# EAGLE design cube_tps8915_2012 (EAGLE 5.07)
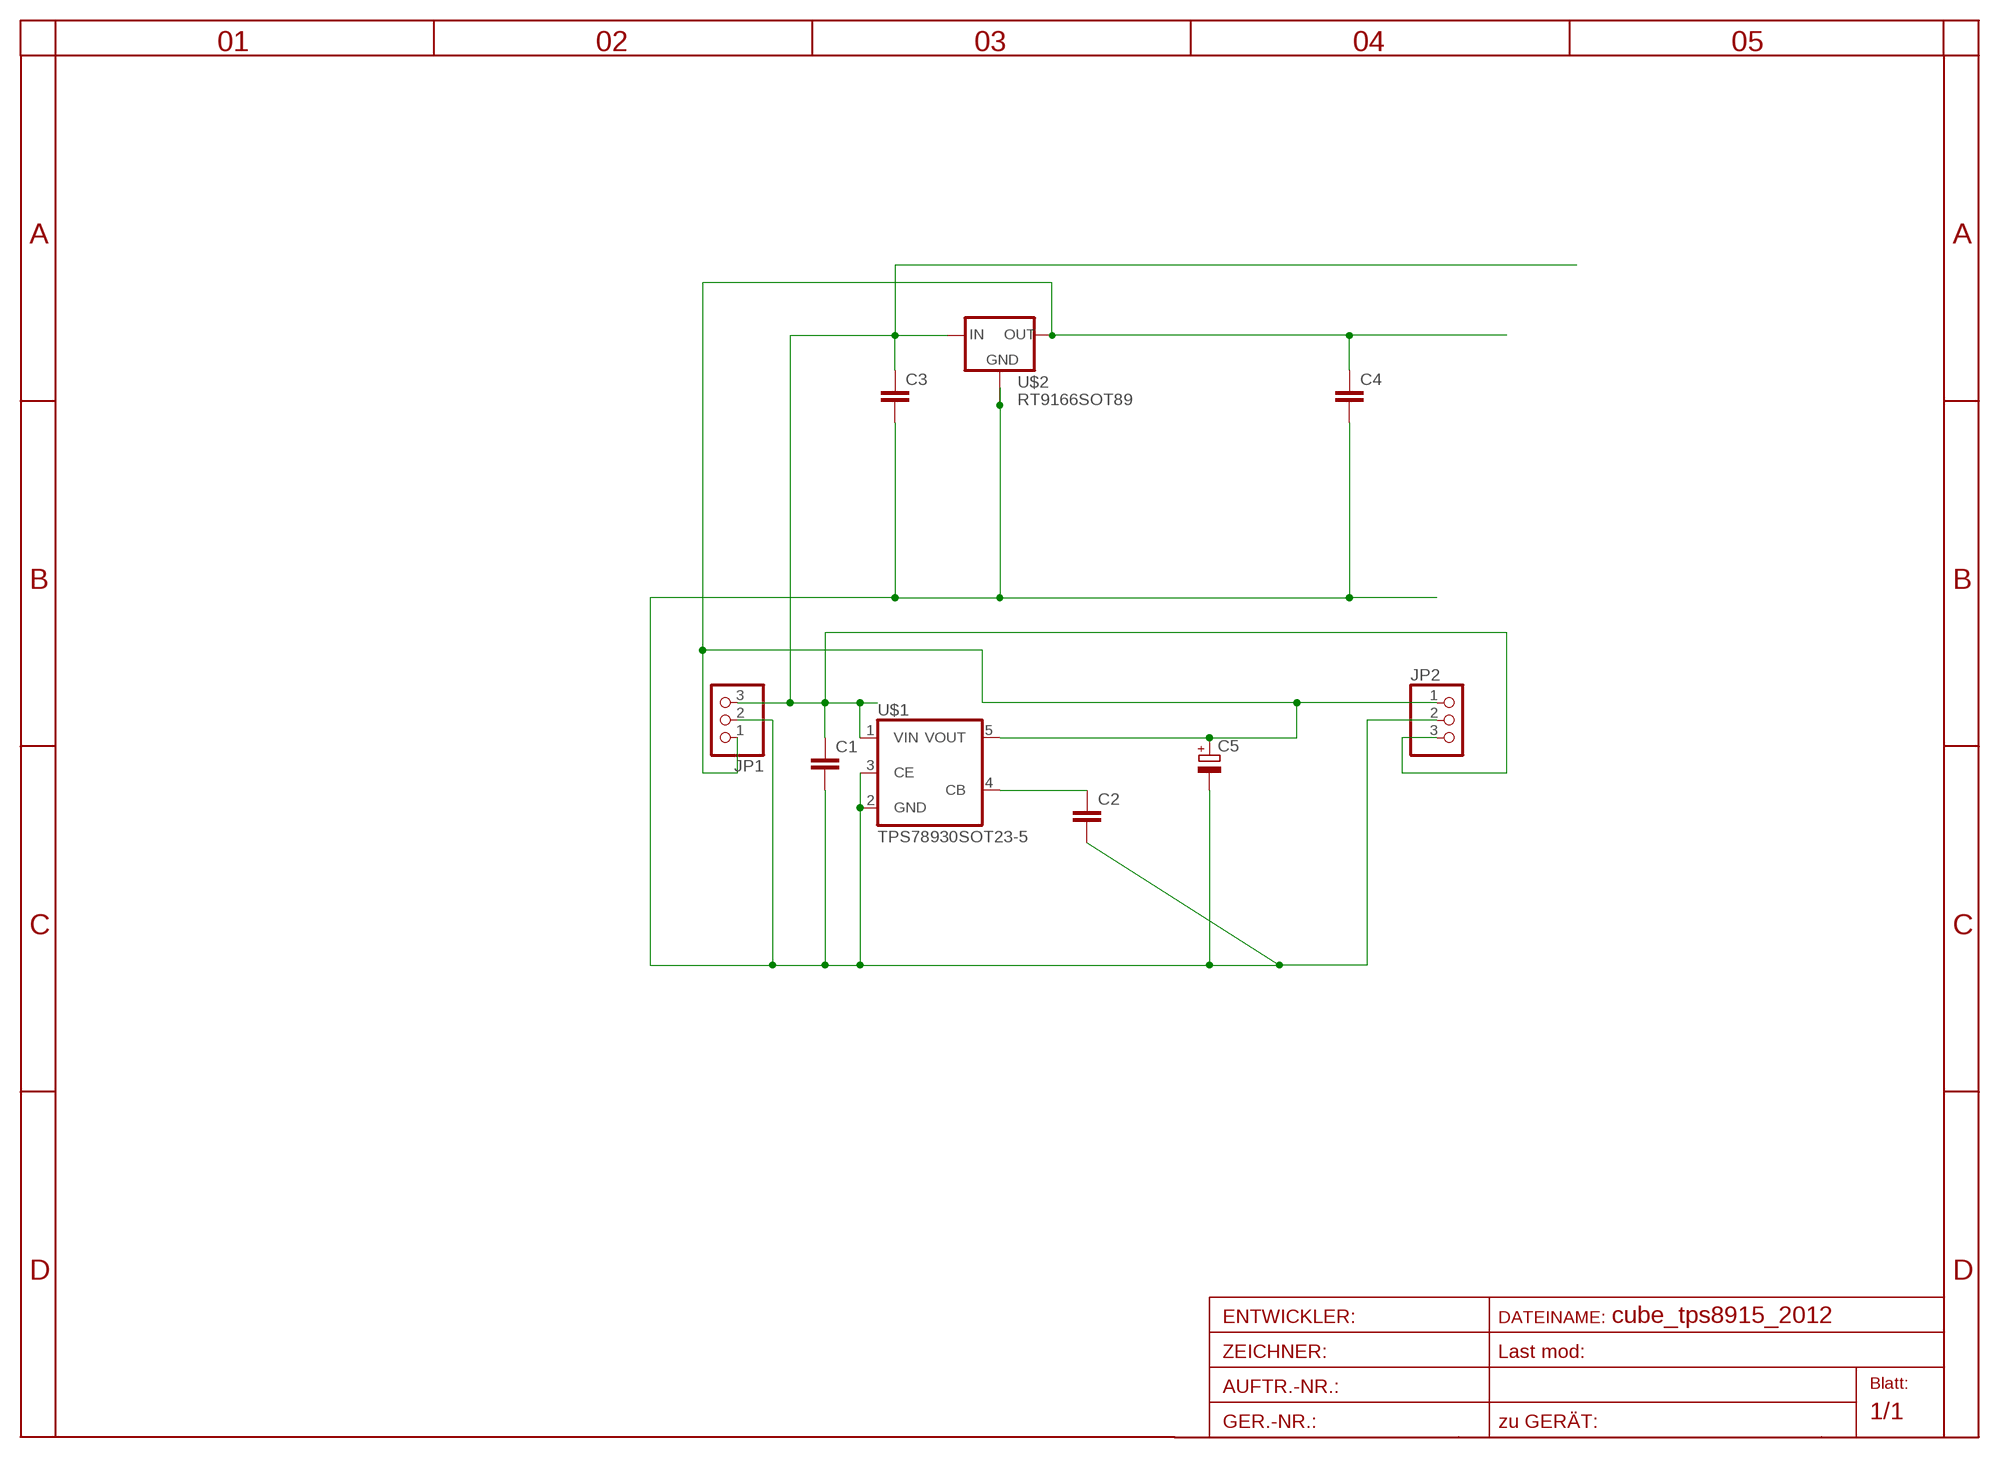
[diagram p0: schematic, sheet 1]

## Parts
C1  C-EUC0805  [C0805]
C2  C-EUC0805  [C0805]
C3  C-EUC1206  [C1206]
C4  C-EUC1206  [C1206]
C5  CPOL-EUCT6032  [CT6032]
JP1  PINHD-1X3  [1X03]
JP2  PINHD-1X3  [1X03]
U$1  TPS78930SOT23-5  [SOT25]
U$2  RT9166SOT89  [SOT89R]

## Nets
GND: C1.2 C2.2 C3.2 C4.2 C5.- JP1.2 JP2.2 U$1.2(GND) U$1.3(CE) U$2.3(GND) U$2.4(GND1)
IN: C1.1 C3.1 JP1.3 JP2.3 U$1.1(VIN) U$2.1(IN)
N$1: C2.1 U$1.4(CB)
OUT: C4.1 C5.+ JP1.1 JP2.1 U$1.5(VOUT) U$2.2(OUT)

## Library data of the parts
C1-C4 = rcl:C-EU: CAPACITOR, European symbol
C5 = rcl:CPOL-EU: POLARIZED CAPACITOR, European symbol
JP1 JP2 = pinhead:PINHD-1X3: PIN HEADER
U$1 = v-reg:TPS78930
U$2 = v-reg:RT9166

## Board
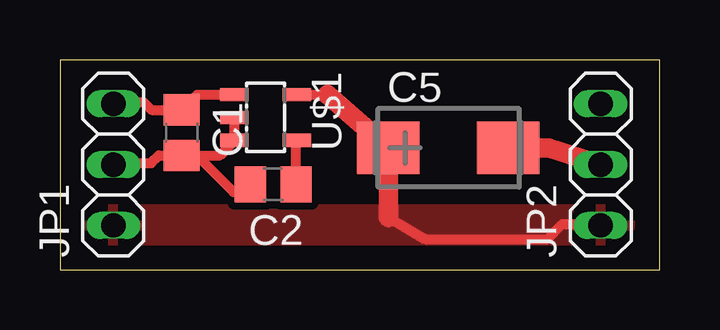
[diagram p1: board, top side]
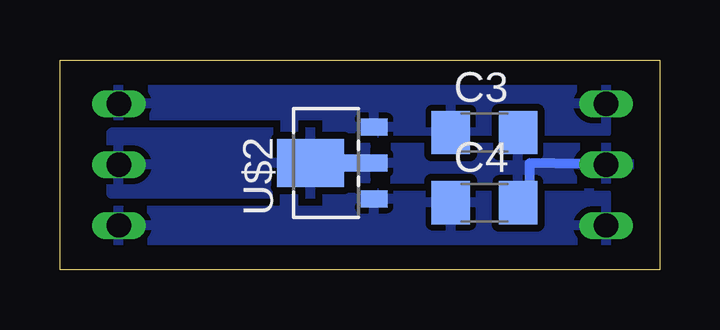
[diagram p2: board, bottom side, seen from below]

Size 25 x 8.75 mm. Coordinates in mm from the lower left corner, seen from the top.
Outline: 0,0 25,0 25,8.75 0,8.75 0,0
Copper layers (1*16): Top 0.035mm / dielectric 1.5mm / Bottom 0.035mm
Design rules "default": minimum track width 10mil, minimum drill 20mil, track to track 8mil, track to pad 8mil, pad to pad 8mil, via to via 8mil, smd to smd 8mil, copper to edge 40mil, drill to drill 8mil, minimum pad ring 1mil, minimum via ring 8mil, stop-mask expansion 4mil, vias tented up to drill 0mil, thermal gap 10mil

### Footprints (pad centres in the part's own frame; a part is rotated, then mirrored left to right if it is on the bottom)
C0805 = smd 1.3 x 1.5: 1 -0.95,0; 2 0.95,0
C1206 = smd 1.6 x 1.8: 1 -1.4,0; 2 1.4,0
CT6032 = smd 2.6 x 2.2: + -2.5,0; - 2.5,0
1X03 = drill 1.016 long: 1 -2.54,0; 2 0,0; 3 2.54,0
SOT25 = smd 0.55 x 1.2: 1 -0.95,-1.3; 2 0,-1.3; 3 0.95,-1.3; 4 0.95,1.3; 5 -0.95,1.3
SOT89R = smd 0.7 x 1.1: 1 1.5,-1.75; 2 -1.5,-1.75 | smd 0.7 x 1.8: 3 0,-1.4 | smd 2 x 2.8: 4 0,0.9

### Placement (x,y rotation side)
C1  5.08,5.71 270 top
C2  8.89,3.56 180 top
C3  7.3,5.71 0 bottom
C4  7.3,2.79 0 bottom
C5  16.19,5.08 0 top
JP1  2.22,4.38 90 top
JP2  22.54,4.38 90 top
U$1  8.57,6.35 270 top
U$2  13.65,4.45 90 bottom

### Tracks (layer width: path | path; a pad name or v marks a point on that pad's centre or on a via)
GND
  Top 0.406: JP1.2 2.29,4.45 3.81,4.45 4.13,4.76 C1.2 5.71,4.76 | 5.71,4.76 6.67,4.76 U$1.3 U$1.2 | C2.2 7.24,3.24 5.71,4.76
  Top 0.813: C5.- 20.38,5.08 JP2.2
  Bottom 0.406: C4.2 5.42,2.79 5.42,4.45 JP1.2
  pour Bottom (isolate 0.305): 1.27,5.08 11.43,5.08 12.7,5.71 22.86,5.71 22.86,3.17 13.97,3.17 12.7,3.81 1.27,3.81
IN
  Top 0.406: JP1.3 2.29,6.99 3.49,6.99 3.81,6.67 C1.1 5.71,7.3 U$1.1
  pour Bottom (isolate 0.305, rank 2): 2.22,5.71 2.22,8.26 22.86,8.26 22.86,5.71
N$1
  Top 0.406: C2.1 9.84,5.37 U$1.4
OUT
  Top 0.406: U$1.5 11.15,7.3 | 13.69,2.18 15.24,1.27 20.32,1.27 20.95,1.91 22.48,1.91 JP2.1
  Top 0.813: 11.15,7.3 C5.+ 13.69,2.18
  pour Top (isolate 0.305, rank 2): 0.95,1.59 0.95,2.22 1.27,2.54 23.5,2.54 23.81,2.22 23.81,1.91 23.18,0.64 1.27,0.64
  pour Bottom (isolate 0.305, rank 2): 2.22,0.64 2.22,3.17 22.86,3.17 22.86,0.64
